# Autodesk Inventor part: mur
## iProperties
Created: 2002-09
Part Number: mur
Material: Par défaut
Document SubType Name: Modélisation
Designer: Maison
Control State: 0
Master: False
Checked Out: False
Shininess: 21.0
Length Units: 11269
Angle Units: 11279
Time Units: 11290
Mass Units: 11283
Length Display Precision: 3
Angle Display Precision: 2
Density: 0.0
Volumn: 0.0
Area: 0.0
PropertySet Name: Model Information
Author: Maison
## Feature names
1. Extrusion2
2. Extrusion4
3. Extrusion5
